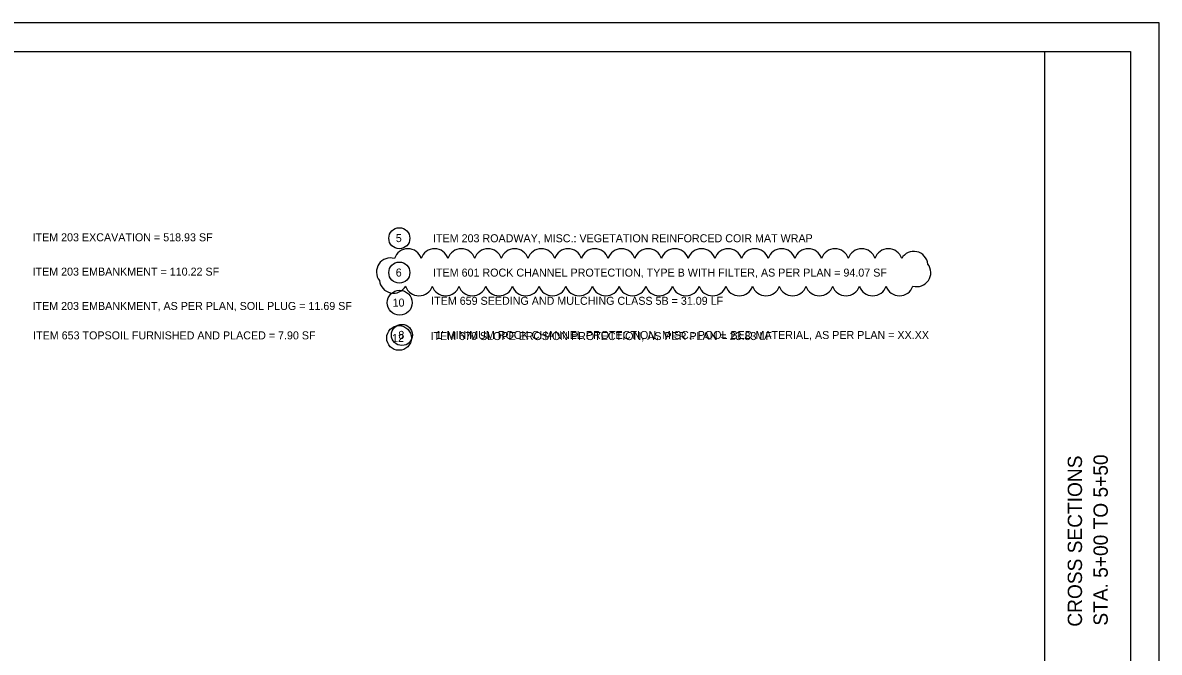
# Model space of a CAD drawing. Extents: x -34.1 to 34, y 0 to 22.
# Drawn here: x 14.14 to 34, y 11 to 22 of the extents above; entities that cross this region are included whole.
import ezdxf

# ---------------------------------------------------------------- set-up
doc = ezdxf.new("R2010")
doc.units = 0
for name, color, linetype in [('CS-ALGN-TEXT', 7, 'Continuous'), ('CS-ANNO', 7, 'Continuous'), ('CS-ANNO-MATC', 7, 'Continuous'), ('CS-ANNO-MATC-TEXT', 7, 'Continuous'), ('CS-ANNO-TABL', 7, 'Continuous')]:
    doc.layers.add(name, color=color, linetype=linetype)

msp = doc.modelspace()

# ---------------------------------------------------------------- linework, layer by layer
at = {"layer": 'CS-ANNO'}
msp.add_lwpolyline([(0, 0), (34, 0), (34, 22), (0, 22)], close=True, dxfattribs=at)
at = {"layer": 'CS-ANNO-MATC'}
msp.add_line((32, 0.5), (32, 21.5), dxfattribs=at)
msp.add_lwpolyline([(1.5, 21.5), (33.5, 21.5), (33.5, 0.5), (1.5, 0.5)], close=True, dxfattribs=at)
at = {"layer": 'CS-ANNO-MATC-TEXT'}
for centre, radius in [((20.718, 18.234), 0.184), ((20.718, 17.634), 0.184), ((20.724, 17.108), 0.218), ((20.713, 16.492), 0.216)]:
    msp.add_circle(centre, radius, dxfattribs=at)
for centre, radius, start, end in [((20.563, 17.646), 0.245, 73.1639, 218.1639), ((20.868, 17.807), 0.245, 17.5538, 162.5538), ((21.334, 17.807), 0.245, 17.5, 162.5), ((21.801, 17.807), 0.245, 17.5, 162.5), ((22.267, 17.807), 0.245, 17.5, 162.5), ((22.734, 17.807), 0.245, 17.5, 162.5), ((23.2, 17.807), 0.245, 17.5, 162.5), ((23.667, 17.807), 0.245, 17.5, 162.5), ((24.133, 17.807), 0.245, 17.5, 162.5), ((24.6, 17.807), 0.245, 17.5, 162.5), ((25.066, 17.807), 0.245, 17.5, 162.5), ((25.533, 17.807), 0.245, 17.5, 162.5), ((25.999, 17.807), 0.245, 17.5, 162.5), ((26.466, 17.807), 0.245, 17.5, 162.5), ((26.932, 17.807), 0.245, 17.5, 162.5), ((27.399, 17.807), 0.245, 17.5, 162.5), ((27.865, 17.807), 0.245, 17.5, 162.5), ((28.332, 17.807), 0.245, 17.5, 162.5), ((28.799, 17.807), 0.245, 17.5, 162.5), ((29.265, 17.807), 0.245, 17.5, 162.5), ((29.711, 17.76), 0.245, 5.5481, 150.5481), ((29.763, 17.633), 0.244, 253.1297, 38.1297), ((20.615, 17.519), 0.245, 185.6594, 330.6594), ((21.061, 17.473), 0.245, 197.5, 342.5), ((21.528, 17.473), 0.245, 197.5, 342.5), ((21.994, 17.473), 0.245, 197.5, 342.5), ((22.461, 17.473), 0.245, 197.5, 342.5), ((22.927, 17.473), 0.245, 197.5, 342.5), ((23.394, 17.473), 0.245, 197.5, 342.5), ((23.86, 17.473), 0.245, 197.5, 342.5), ((24.327, 17.473), 0.245, 197.5, 342.5), ((24.793, 17.473), 0.245, 197.5, 342.5), ((25.26, 17.473), 0.245, 197.5, 342.5), ((25.726, 17.473), 0.245, 197.5, 342.5), ((26.193, 17.473), 0.245, 197.5, 342.5), ((26.659, 17.473), 0.245, 197.5, 342.5), ((27.126, 17.473), 0.245, 197.5, 342.5), ((27.592, 17.473), 0.245, 197.5, 342.5), ((28.059, 17.473), 0.245, 197.5, 342.5), ((28.525, 17.473), 0.245, 197.5, 342.5), ((28.992, 17.473), 0.245, 197.5, 342.5), ((29.459, 17.473), 0.245, 197.5, 342.5)]:
    msp.add_arc(centre, radius, start, end, dxfattribs=at)
at = {"layer": 'CS-ANNO-TABL'}
msp.add_circle((20.763, 16.544), 0.184, dxfattribs=at)

# ---------------------------------------------------------------- texts
at = {"layer": 'CS-ALGN-TEXT'}
for s, p in [('CROSS SECTIONS', (32.65, 11.447)), ('STA. 5+00 TO 5+50', (33.1, 11.465))]:
    msp.add_text(s, height=0.25, rotation=90, dxfattribs=at).set_placement(p)
at = {"layer": 'CS-ANNO-MATC-TEXT'}
for s, p in [('ITEM 203 EXCAVATION = 518.93 SF', (14.307, 18.181)), ('5', (20.656, 18.167)), ('ITEM 203 ROADWAY, MISC.: VEGETATION REINFORCED COIR MAT WRAP', (21.307, 18.164)), ('ITEM 203 EMBANKMENT = 110.22 SF', (14.307, 17.581)), ('6', (20.655, 17.565)), ('ITEM 601 ROCK CHANNEL PROTECTION, TYPE B WITH FILTER, AS PER PLAN = 94.07 SF', (21.307, 17.564)), ('ITEM 203 EMBANKMENT, AS PER PLAN, SOIL PLUG = 11.69 SF', (14.307, 16.981)), ('ITEM 659 SEEDING AND MULCHING CLASS 5B = 31.09 LF', (21.274, 17.071)), ('ITEM 653 TOPSOIL FURNISHED AND PLACED = 7.90 SF', (14.317, 16.467)), ('ITEM 670 SLOPE EROSION PROTECTION, AS PER PLAN = 23.83 LF', (21.263, 16.455))]:
    msp.add_text(s, height=0.14, dxfattribs=at).set_placement(p)
for s, p in [('10', (20.601, 17.037)), ('12', (20.591, 16.419))]:
    msp.add_text(s, height=0.14, rotation=1, dxfattribs=at).set_placement(p)
at = {"layer": 'CS-ANNO-TABL'}
for s, p in [('8', (20.701, 16.475)), ("1' MINIMUM ROCK CHANNEL PROTECTION, MISC.: POOL BED MATERIAL, AS PER PLAN = XX.XX", (21.352, 16.474))]:
    msp.add_text(s, height=0.14, dxfattribs=at).set_placement(p)

doc.saveas('drawing.dxf')
